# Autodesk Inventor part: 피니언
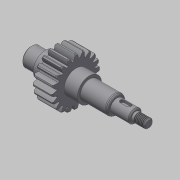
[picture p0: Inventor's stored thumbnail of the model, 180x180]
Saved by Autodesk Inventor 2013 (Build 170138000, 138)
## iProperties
Created: 2019-06
Part Number: 피니언
Material: 스테인리스강
Document SubType Name: Modeling
Designer: mduedu
Density: 8.08 g/cm^3
Mass: 336.3 g
Surface Area: 112.617 cm^2
Volume: 41.6213 cm^3
Author: mduedu
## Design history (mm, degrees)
sketch "스케치1"
  geometry: L1 (0, 0)-(13, 0); L2 (13, 0)-(13, 8.5); L3 (13, 8.5)-(0, 8.5); L4 (0, 8.5)-(0, 0); L5 (13, 0)-(53, 0); L6 (53, 0)-(53, 11); L7 (53, 11)-(13, 11); L8 (13, 11)-(13, 0); L9 (53, 0)-(78, 0); L10 (78, 0)-(78, 8.5); L11 (78, 8.5)-(53, 8.5); L12 (53, 8.5)-(53, 0); L13 (78, 0)-(95, 0); L14 (95, 0)-(95, 6); L15 (95, 6)-(78, 6); L16 (78, 6)-(78, 0); L17 (95, 0)-(107, 0); L18 (107, 0)-(107, 4); L19 (107, 4)-(95, 4); L20 (95, 4)-(95, 0)
  constraints: 40 end point, 10 parallel, 5 horizontal, 5 perpendicular
  dimensions: "d0" = 107 distance between parallel lines of L18 L4; "d2" = 78 distance between parallel lines of L10 L4; "d3" = 40 distance of L6.end L7.end; "d4" = 25 distance of L10.end L11.end; "d5" = 17 distance of L14.end L15.end; "d6" = 8 diameter of L19 L17; "d7" = 12 diameter of L15 L13; "d8" = 17 diameter of L11 L9; "d9" = 22 diameter of L7 L5; "d10" = 17 diameter of L3 L1
revolve "회전1" sketch "스케치1" stored, may be unused: angle "d11" = 90 deg
node "작업 평면1"
sketch "스케치2"
  geometry: C1 r 17.5 at (0, 0); C2 r 20 at (0, 0); C3 r 22 at (0, 0); 1 further point
  constraints: 3 centre point, 3 coincident
  dimensions: "d13" = 40 diameter of C2; "d15" = 44 diameter of C3; "d16" = 35 diameter of C1
extrude "돌출1" join sketch "스케치2" distance "d17" = 18; taper "d18" = 0 deg
sketch "스케치3"
  geometry: L1 (0, 0)-(22, 0); L2 (0, 0)-(0, 22); L3 (0.57, 0)-(0.57, 22); L4 (1.57, 0)-(1.57, 22); L5 (2.07, 0)-(2.07, 22); A1 r 22 centre (0, 0) between (22, 0) and (0, 22) reference; A2 r 9.495 centre (-7.411, 16.856) between (2.07, 17.377) and (0.57, 22); A3 r 9.495 centre (7.411, 16.856) between (-0.57, 22) and (-2.07, 17.377); A4 r 17.5 centre (0, 0) between (2.07, 17.377) and (-2.07, 17.377); A5 r 22.007 centre (0, 0) between (0.57, 22) and (-0.57, 22); 4 further points
  constraints: 11 point on circle, 10 end point, 6 parallel, 5 point on line, 4 centre point, 3 symmetric about line, 2 coincident, 1 horizontal, 1 perpendicular, 5 other
  dimensions: "d19" = 0.5 distance between parallel lines of L5 L4; "d21" = 1 distance between parallel lines of L3 L4; "d22" = 1.57 distance between parallel lines of L2 L4
extrude "돌출2" join sketch "스케치3" stored distance "d23" = 18; taper "d24" = 0 deg
chamfer "모따기1" distance "d25" = 1; stored, may be unused: second distance "d26" = 2, angle "d27" = 45 deg
fillet "모깎기1" dims "d31" = 0.3
chamfer "모따기2" distance "d32" = 1; stored, may be unused: second distance "d33" = 2, angle "d34" = 45 deg
node "작업 평면2"
sketch "스케치4"
  geometry: L1 (3.5, -2)-(-2.5, -2); L2 (-2.5, 2)-(3.5, 2); L3 (8.5, 8.5)-(8.5, -8.5) reference; A1 r 2 centre (3.5, 0) between (3.5, -2) and (3.5, 2); A2 r 2 centre (-2.5, 0) between (-2.5, 2) and (-2.5, -2); 1 further point
  constraints: 4 end point, 4 point on circle, 4 tangent, 2 centre point, 1 horizontal, 1 horizontal alignment, 1 parallel
  dimensions: "d35" = 3 distance edge to line of A1 L3; "d36" = 10 dimension on A2 A1; "d37" = 4 distance between parallel lines of L2 L1
extrude "돌출3" cut sketch "스케치4" distance "d38" = 2.5; taper "d39" = 0 deg
chamfer "모따기3" distance "d40" = 1.82; stored, may be unused: second distance "d41" = 2, angle "d42" = 30 deg
fillet "모깎기2" dims "d43" = 1, "d44" = 2
chamfer "모따기4" distance "d45" = 1; stored, may be unused: second distance "d46" = 2, angle "d47" = 30 deg
feature "스레드1" dims "d48" = 10, "d49" = 0
chamfer "모따기5" distance "d50" = 1; stored, may be unused: second distance "d51" = 2, angle "d52" = 30 deg
node "솔리드1"
pattern_circular "원형 패턴1" dims angle "d29" = 360 deg
other parameters: "d12" = -12
